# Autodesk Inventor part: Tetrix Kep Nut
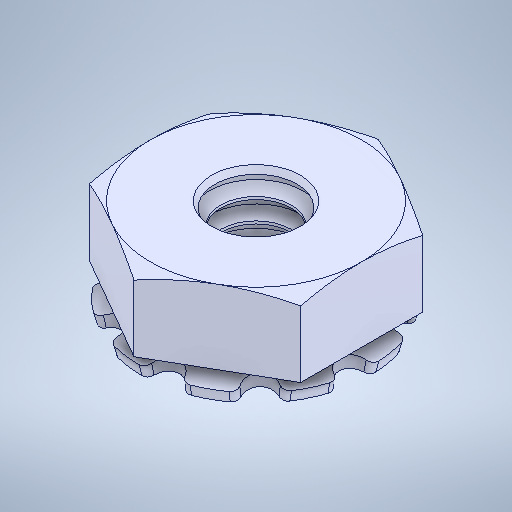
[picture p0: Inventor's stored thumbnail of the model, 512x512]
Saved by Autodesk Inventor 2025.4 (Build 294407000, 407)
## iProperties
Created: 2021-10
Part Number: Tetrix Kep Nut
Material: Genérico
Document SubType Name: Modeling
Designer: usuario
Density: 1 g/cm^3
Appearance: Valor por defecto
Author: usuario
Sending System: SolidWorks 2016
Last Author: LENOVO
Last Saved: 2021-10-22
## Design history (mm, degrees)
fillet "Fillet1"
node "Plane1"
node "Sólido1"
